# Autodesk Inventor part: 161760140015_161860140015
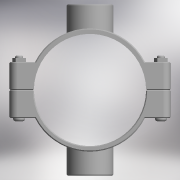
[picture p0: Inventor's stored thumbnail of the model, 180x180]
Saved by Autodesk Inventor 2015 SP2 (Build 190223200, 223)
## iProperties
Created: 2017-05
Part Number: 161760140015_161860140015
Material: Generic
Description: PLASSON DOUBLE SADDLE 140-1.1/2"
Document SubType Name: Modeling
Designer: KIM
Density: 1 g/cm^3
Appearance: Default
Author: KIM
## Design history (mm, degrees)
derived "16176.ipt"
feature "Solid1::16176.ipt"
feature "Solid2::16176.ipt"
tag "TaggingFeature1"
body "Solid1"
body "Solid2"
other parameters: "d0" = 154, "d1" = 201, "d4" = 136, "d5" = 0, "d6" = 10.05, "d7" = 201, "d8" = 0.1, "d10" = 0, "d11" = 1.4, "d20" = 1.4, "d23" = 1.4, "d36" = 15, "d37" = 12, "d38" = 78, "d39" = 0, "d40" = 3, "d41" = 5, "d42" = 0, "d44" = 3, "d45" = 0, "d46" = 1.4, "d52" = 44.845, "d53" = 25, "d54" = 0, "d57" = 0, "d58" = 151.2, "d60" = 0, "d62" = 15, "d63" = 12, "d66" = 112, "d67" = 214, "d68" = 58.2985, "d69" = 44.845, "d70" = 25, "d71" = 0, "d74" = 0, "d75" = 1.4, "G_" = 44.845, "A_" = 107, "L_" = 201, "L_1" = 136, "l_2" = 25
